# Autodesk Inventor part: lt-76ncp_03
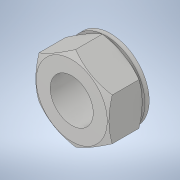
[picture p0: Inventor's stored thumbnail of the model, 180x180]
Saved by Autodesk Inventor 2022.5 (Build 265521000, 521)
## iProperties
Created: 2021-11
Part Number: lt-76ncp_03
Material: 一般
Document SubType Name: Modeling
Designer: ImaoCorp
Density: 1 g/cm^3
Appearance: 既定
Author: ImaoCorp
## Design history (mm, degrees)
feature "lt-76ncp_03"
node "ソリッド1"
